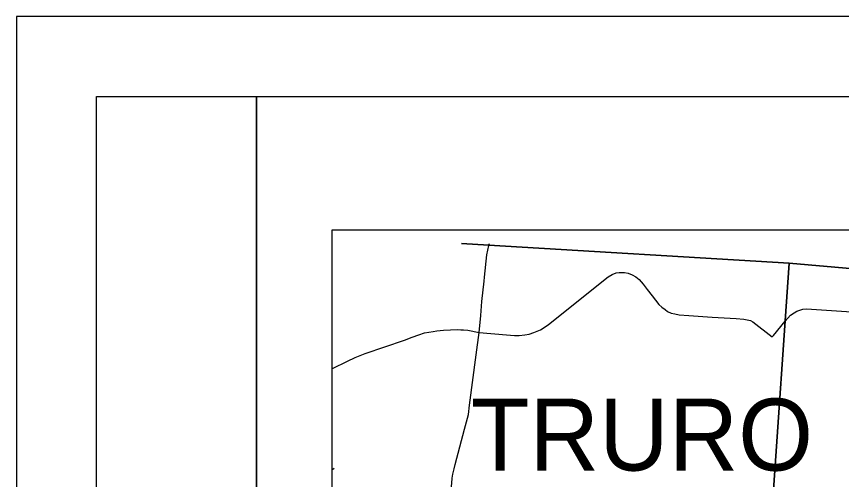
# Model space of a CAD drawing. Extents: x 1880545 to 1948545, y 79309 to 723051.
# Drawn here: x 1880545 to 1890853, y 717259 to 723051 of the extents above; entities that cross this region are included whole.
import ezdxf

# ---------------------------------------------------------------- set-up
doc = ezdxf.new("R2010")
doc.units = 0
for name, color, linetype in [('GM_X_City_Street', 7, 'Continuous'), ('GM_X_County', 7, 'Continuous'), ('GM_X_County_Road', 7, 'Continuous'), ('GM_X_Township', 7, 'Continuous'), ('GM_X_Township_Road', 7, 'Continuous'), ('GM_X_Township_Text', 7, 'Continuous'), ('SH_Border', 7, 'Continuous'), ('SH_Cut_Line', 7, 'Continuous'), ('SH_Text', 7, 'Continuous')]:
    doc.layers.add(name, color=color, linetype=linetype)

msp = doc.modelspace()

# ---------------------------------------------------------------- linework, layer by layer
at = {"layer": 'GM_X_City_Street'}
msp.add_line((1884485, 717379), (1884516, 717401), dxfattribs=at)
msp.add_lwpolyline([(1890151, 719240), (1890216, 719314), (1890263, 719345), (1890295, 719366), (1890370, 719389), (1890418, 719394), (1891105, 719346), (1891930, 719294), (1892041, 719284), (1892095, 719268), (1892147, 719248), (1892183, 719223), (1892219, 719187), (1892352, 718988), (1892405, 718947), (1892463, 718913), (1892561, 718891), (1892879, 718872)], dxfattribs=at)
at = {"layer": 'GM_X_County'}
msp.add_lwpolyline([(1891843, 720212), (1891817, 719823), (1890200, 719967), (1890150, 719243), (1889940, 716226), (1889896, 715604), (1889789, 714059), (1889789, 714057), (1889728, 713178), (1889728, 713177), (1889680, 712485), (1889677, 712442), (1889513, 710095), (1889456, 709272), (1889272, 706620), (1886741, 706793), (1884485, 706947)], dxfattribs=at)
at = {"layer": 'GM_X_County_Road'}
for points in [[(1886394, 719788), (1886422, 720071), (1886446, 720187), (1886453, 720212)], [(1886346, 719310), (1886361, 719484), (1886389, 719741), (1886394, 719788)], [(1885910, 715859), (1885931, 716341), (1885961, 716830), (1885977, 717132), (1885983, 717214), (1885990, 717276), (1885998, 717324), (1886014, 717394), (1886028, 717448), (1886144, 717890), (1886191, 718072), (1886206, 718189), (1886290, 718819), (1886327, 719099), (1886346, 719310)]]:
    msp.add_lwpolyline(points, dxfattribs=at)
at = {"layer": 'GM_X_Township'}
for points in [[(1886104, 720212), (1886445, 720189), (1890200, 719967), (1890150, 719243), (1889940, 716226), (1889896, 715604), (1889789, 714059), (1889789, 714057), (1889728, 713178), (1889728, 713177), (1889680, 712485), (1889677, 712442), (1889513, 710095), (1889456, 709272), (1889272, 706620), (1886741, 706793), (1884485, 706947)], [(1891843, 720212), (1891817, 719823), (1890200, 719967), (1886445, 720189), (1886104, 720212)], [(1889272, 706620), (1889456, 709272), (1889513, 710095), (1889677, 712442), (1889680, 712485), (1889728, 713177), (1889728, 713178), (1889789, 714057), (1889789, 714059), (1889896, 715604), (1889940, 716226), (1890150, 719243), (1890200, 719967), (1891817, 719823), (1893081, 719771), (1893522, 719763), (1894775, 719644), (1896793, 719532), (1896834, 719533), (1897456, 719507), (1898145, 719477), (1899877, 719378), (1904377, 719099)]]:
    msp.add_lwpolyline(points, dxfattribs=at)
at = {"layer": 'GM_X_Township_Road'}
for points in [[(1886327, 719099), (1886669, 719067), (1886767, 719059), (1886824, 719059), (1886897, 719068), (1886952, 719078), (1887011, 719097), (1887052, 719113), (1887091, 719133), (1887188, 719195), (1887423, 719380), (1887938, 719796), (1887986, 719825), (1888037, 719844), (1888075, 719848), (1888110, 719849), (1888140, 719848), (1888186, 719840), (1888239, 719820), (1888284, 719794), (1888326, 719760), (1888375, 719703), (1888424, 719636), (1888486, 719555), (1888570, 719450), (1888610, 719414), (1888649, 719385), (1888680, 719362), (1888726, 719341), (1888770, 719330), (1888823, 719320), (1888946, 719309), (1889236, 719289), (1889537, 719271), (1889631, 719265), (1889675, 719257), (1889715, 719246), (1889745, 719231), (1889988, 719042), (1890005, 719060), (1890151, 719240)], [(1884817, 718802), (1884902, 718835), (1885392, 719002), (1885487, 719038), (1885573, 719070), (1885643, 719092), (1885698, 719104), (1885751, 719112), (1885796, 719118), (1885879, 719125), (1886056, 719135), (1886096, 719133), (1886131, 719133), (1886184, 719127), (1886327, 719099)], [(1884485, 718644), (1884493, 718647), (1884680, 718740), (1884777, 718787), (1884817, 718802)]]:
    msp.add_lwpolyline(points, dxfattribs=at)
at = {"layer": 'SH_Border'}
for points in [[(1881545, 722051), (1883545, 722051), (1883545, 680051), (1881545, 680051)], [(1883545, 722051), (1947545, 722051), (1947545, 680051), (1883545, 680051)]]:
    msp.add_lwpolyline(points, close=True, dxfattribs=at)
at = {"layer": 'SH_Cut_Line'}
msp.add_lwpolyline([(1880545, 679051), (1948545, 679051), (1948545, 723051), (1880545, 723051)], close=True, dxfattribs=at)
at = {"layer": 'SH_Text'}
msp.add_lwpolyline([(1884490, 720381), (1928141, 720381), (1928141, 691152), (1884490, 691152)], close=True, dxfattribs=at)

# ---------------------------------------------------------------- texts
at = {"layer": 'GM_X_Township_Text'}
msp.add_text('TRURO', height=900, rotation=0, dxfattribs=at).set_placement((1886220, 717371))

doc.saveas('drawing.dxf')
